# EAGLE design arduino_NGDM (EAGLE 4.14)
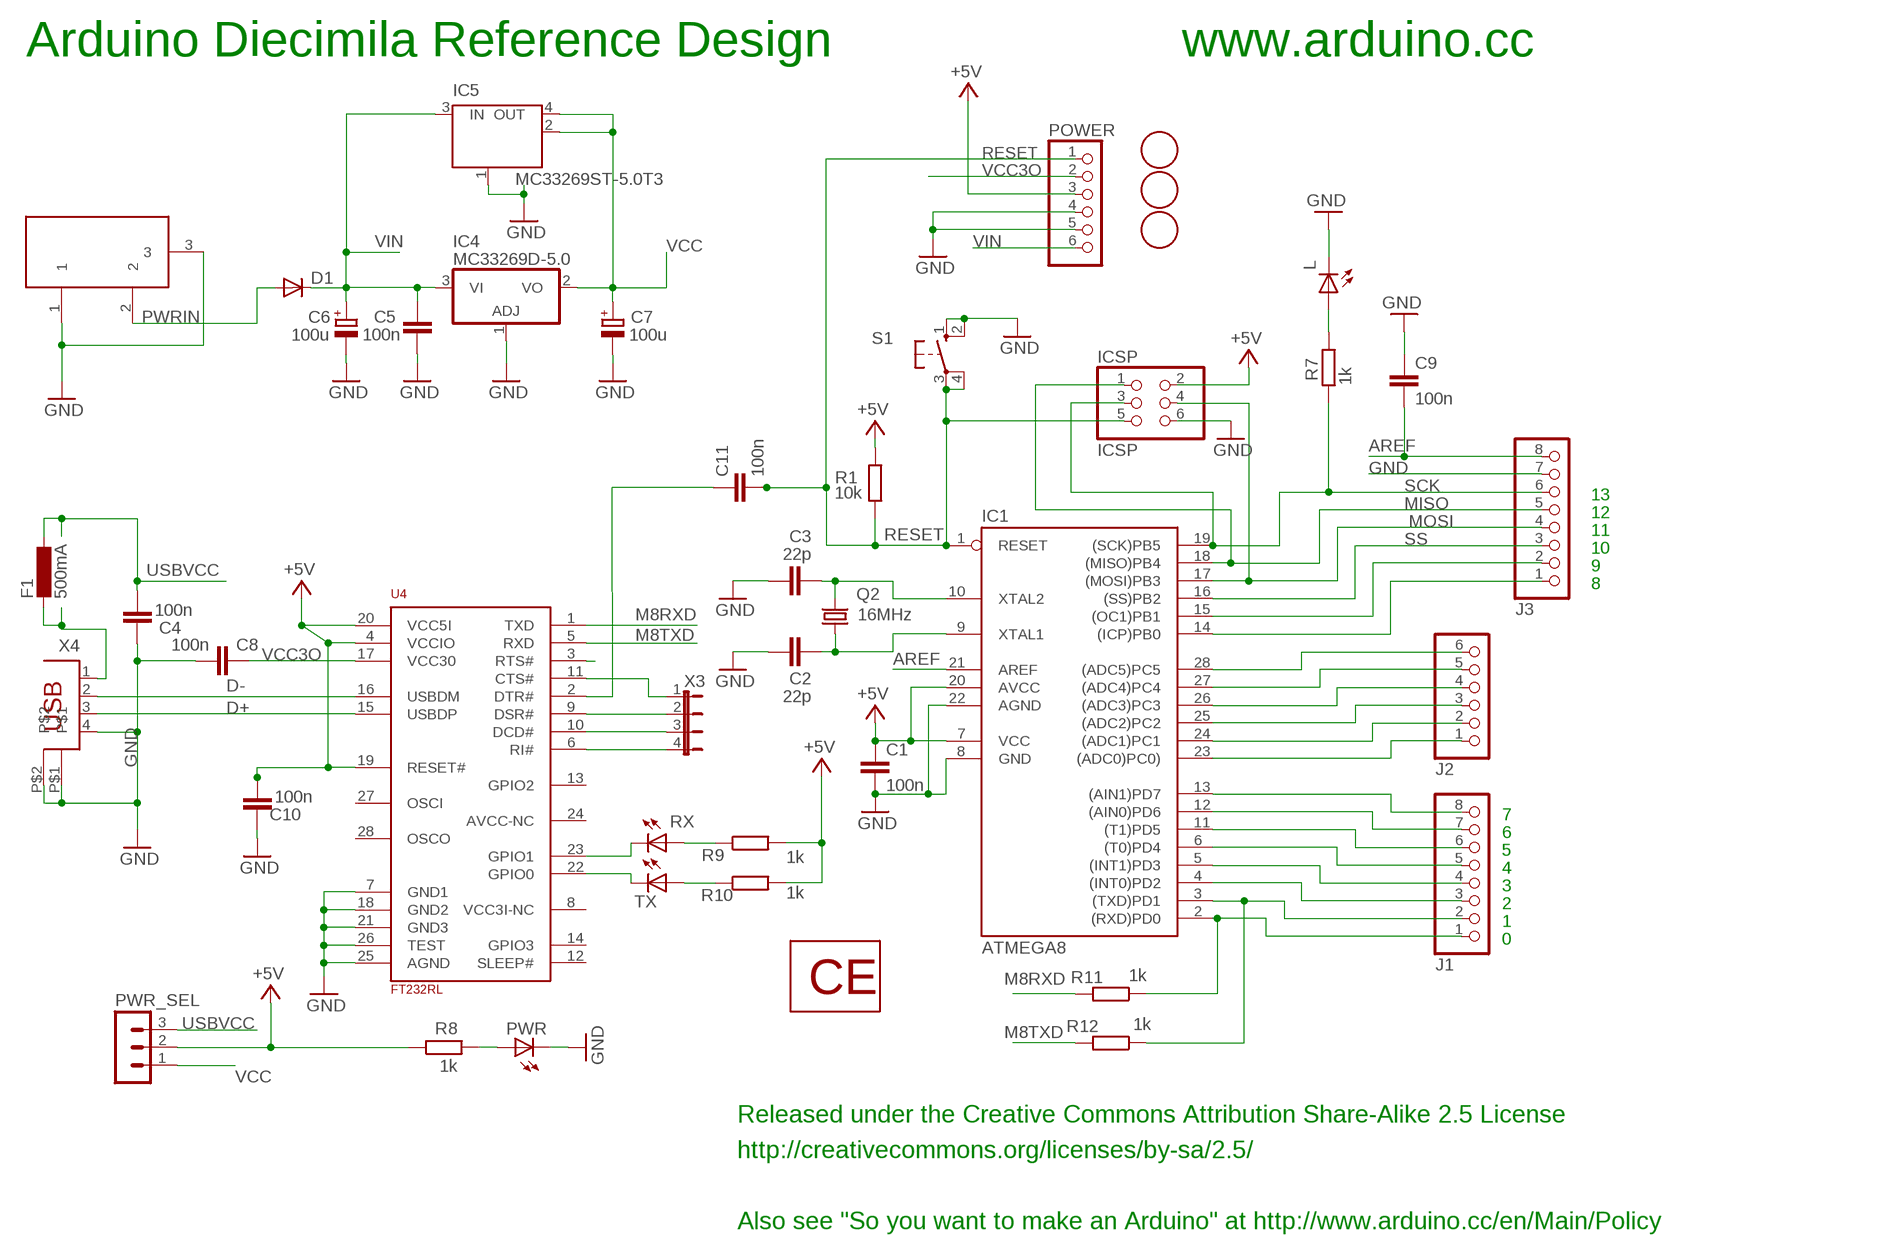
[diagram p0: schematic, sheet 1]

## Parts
C1  100n  C-EU  [C0805RND]
C2  22p  C-EU  [C0805RND]
C3  22p  C-EU  [C0805RND]
C4  100n  C-EU  [C0805RND]
C5  100n  C-EU  [C0805RND]
C6  100u  CPOL-EUD  [PANASONIC_D]
C7  100u  CPOL-EUD  [PANASONIC_D]
C8  100n  C-EU  [C0805RND]
C9  100n  C-EU  [C0805RND]
C10  100n  C-EU  [C0805RND]
C11  100n  C-EU  [C0805RND]
D1  DIODE-SMB  [SMB]
F1  500mA  L-EUL1812  [L1812]
IC1  ATMEGA8  AT90S4433P  [DIL28-3]
IC4  MC33269D-5.0  [DPACK]
IC5  MC33269ST-5.0T3  MC33269ST-3.3T3  [SOT223]
ICSP  ICSP  PINHD-2X3  [2X03]
J1  PINHD-1X8  [1X08]
J2  PINHD-1X6  [1X06]
J3  PINHD-1X8  [1X08]
L  LED0805ROUND  [0805RND]
POWER  PINHD-1X6  [1X06]
PWR  LED0805ROUND  [0805RND]
PWR_SEL  MA03-1  [MA03-1]
Q2  16MHz  CRYTALHC49S  [HC49/S]
R1  10k  R-EU_  [R0805RND]
R7  1k  R-EU_  [R0805RND]
R8  1k  R-EU_  [R0805RND]
R9  1k  R-EU_  [R0805RND]
R10  1k  R-EU_  [R0805RND]
R11  1k  R-EU_  [R0805RND]
R12  1k  R-EU_  [R0805RND]
RX  LED0805ROUND  [0805RND]
S1  10-XX  [B3F-10XX]
TX  LED0805ROUND  [0805RND]
U4  FT232RL  [SSOP28]
U$1  FIDUCIALMOUNT  [FIDUCIA-MOUNT]
U$2  FIDUCIALMOUNT  [FIDUCIA-MOUNT]
U$3  FIDUCIALMOUNT  [FIDUCIA-MOUNT]
U$4  CE  [CE-COPPER]
X2  DC21MMX  [DC-21MM]
X3  JP4E  [JP4]
X4  PN61729  [PN61729]

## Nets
+5V [usbvcc]: C1.1 C10.1 IC1.7(VCC) IC1.20(AVCC) ICSP.2 POWER.3 PWR_SEL.2 R1.2 R8.1 R9.2 R10.2 U4.4(VCCIO) U4.19(RESET#) U4.20(VCC5I)
AREF [aref]: C9.2 IC1.21(AREF) J3.8
D+: U4.15(USBDP) X4.3
D-: U4.16(USBDM) X4.2
GND [gnd]: C1.2 C2.1 C3.1 C4.2 C5.1 C6.- C7.- C8.1 C9.1 C10.2 IC1.8(GND) IC1.22(AGND) IC4.1(ADJ) IC5.1(GND/ADJ) ICSP.6 J3.7 L.P$2(C) POWER.4 POWER.5 PWR.P$2(C) S1.1(S) S1.2(S1) U4.7(GND1) U4.18(GND2) U4.21(GND3) U4.25(AGND) U4.26(TEST) X2.1 X2.3 X4.4 X4.P$1 X4.P$2
M8RXD: R11.2 U4.1(TXD)
M8TXD: R12.2 U4.5(RXD)
MISO: IC1.18((MISO)PB4) ICSP.1 J3.5
MOSI: IC1.17((MOSI)PB3) ICSP.4 J3.4
N$2: L.P$1(A) R7.1
N$3: PWR.P$1(A) R8.2
N$5: IC1.14((ICP)PB0) J3.1
N$6: C2.2 IC1.9(XTAL1) Q2.1
N$7: C3.2 IC1.10(XTAL2) Q2.2
N$8 [usbvcc]: F1.2 X4.1
N$9: U4.3(RTS#)
N$10: IC1.4((INT0)PD2) J1.3
N$11: IC1.5((INT1)PD3) J1.4
N$12: IC1.6((T0)PD4) J1.5
N$13: IC1.11((T1)PD5) J1.6
N$14: IC1.12((AIN0)PD6) J1.7
N$15: IC1.13((AIN1)PD7) J1.8
N$16: IC1.23((ADC0)PC0)) J2.1
N$17: IC1.24((ADC1)PC1) J2.2
N$18: IC1.25((ADC2)PC2) J2.3
N$19: IC1.26((ADC3)PC3) J2.4
N$20: IC1.27((ADC4)PC4) J2.5
N$21: IC1.28((ADC5)PC5) J2.6
N$22: IC1.15((OC1)PB1) J3.2
N$24: C11.1 U4.2(DTR#)
N$32: RX.P$2(C) U4.23(GPIO1)
N$34: TX.P$2(C) U4.22(GPIO0)
N$35: R9.1 RX.P$1(A)
N$36: R10.1 TX.P$1(A)
N$37: U4.6(RI#) X3.4
N$38: U4.10(DCD#) X3.3
N$39: U4.11(CTS#) X3.1
N$40: U4.9(DSR#) X3.2
PD0: IC1.2((RXD)PD0) J1.1 R11.1
PD1: IC1.3((TXD)PD1) J1.2 R12.1
PWRIN [power]: D1.A X2.2
RESET: C11.2 IC1.1(RESET) ICSP.5 POWER.1 R1.1 S1.3(P) S1.4(P1)
SCK: IC1.19((SCK)PB5) ICSP.3 J3.6 R7.2
SS: IC1.16((SS)PB2) J3.3
USBVCC [usbvcc]: C4.1 F1.1 PWR_SEL.3
VCC [usbvcc]: C7.+ IC4.2(VO) IC5.2(OUT) IC5.4(OUT) PWR_SEL.1
VCC3O: C8.2 POWER.2 U4.17(VCC30)
VIN [power]: C5.2 C6.+ D1.C IC4.3(VI) IC5.3(IN) POWER.6
Unconnected: U4.8(VCC3I-NC) U4.12(SLEEP#) U4.13(GPIO2) U4.14(GPIO3) U4.24(AVCC-NC) U4.27(OSCI) U4.28(OSCO)

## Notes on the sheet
- Arduino Diecimila Reference Design | www.arduino.cc
- 13
- 12
- 11
- 10
- 9
- 8
- 7
- 6
- 5
- 4
- 3
- 2
- 1
- 0
- Released under the Creative Commons Attribution Share-Alike 2.5 License
- http://creativecommons.org/licenses/by-sa/2.5/
- Also see "So you want to make an Arduino" at http://www.arduino.cc/en/Main/Policy

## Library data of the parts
C1-C5 C8-C11 = rcl:C-EU: CAPACITOR, European symbol
C6 C7 = rcl:CPOL-EU: POLARIZED CAPACITOR, European symbol
D1 = diode:DIODE-: DIODE
F1 = rcl:L-EU: INDUCTOR, European symbol
IC1 = atmel:AT90S4433: MICROCONTROLLER 4 Kbytes FLASH 128 bytes SRAM 256 bytes EEPROM UART 6-channel 10 bit ADC
IC4 = linear:MC33269?*: Adjustable Output Low Dropout Voltage Regulator 800 mA Source: http://www.onsemi.com/pub/Collateral/MC33269-D.PDF
IC5 = linear:MC33269ST*: Adjustable Output Low Dropout Voltage Regulator 800 mA Source: http://www.onsemi.com/pub/Collateral/MC33269-D.PDF
ICSP = pinhead:PINHD-2X3: PIN HEADER
J1 J3 = pinhead:PINHD-1X8: PIN HEADER
J2 POWER = pinhead:PINHD-1X6: PIN HEADER
L PWR RX TX = led:LED: LED
PWR_SEL = con-lstb:MA03-1: PIN HEADER
Q2 = crystal:CRYTAL: CRYSTAL
R1 R7-R12 = rcl:R-EU_: RESISTOR, European symbol
S1 = switch-omron:10-XX: OMRON SWITCH
U4 = SmartPrj:FT232RL
U$1-U$3 = SmartPrj:FIDUCIALMOUNT
U$4 = SmartPrj:CE
X2 = powersupply:DC21MM
X3 = jumper:JP4E: JUMPER
X4 = SmartPrj:PN61729: BERG USB connector

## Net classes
0 default: width 0.254 mm, drill 0.254 mm
1 power: width 0.61 mm, drill 0.33 mm, clearance 0.711 mm
2 gnd: width 0.305 mm, drill 0.254 mm, clearance 0.711 mm
3 usbvcc: width 0.508 mm, drill 0.254 mm, clearance 0.711 mm
4 aref: width 0.406 mm

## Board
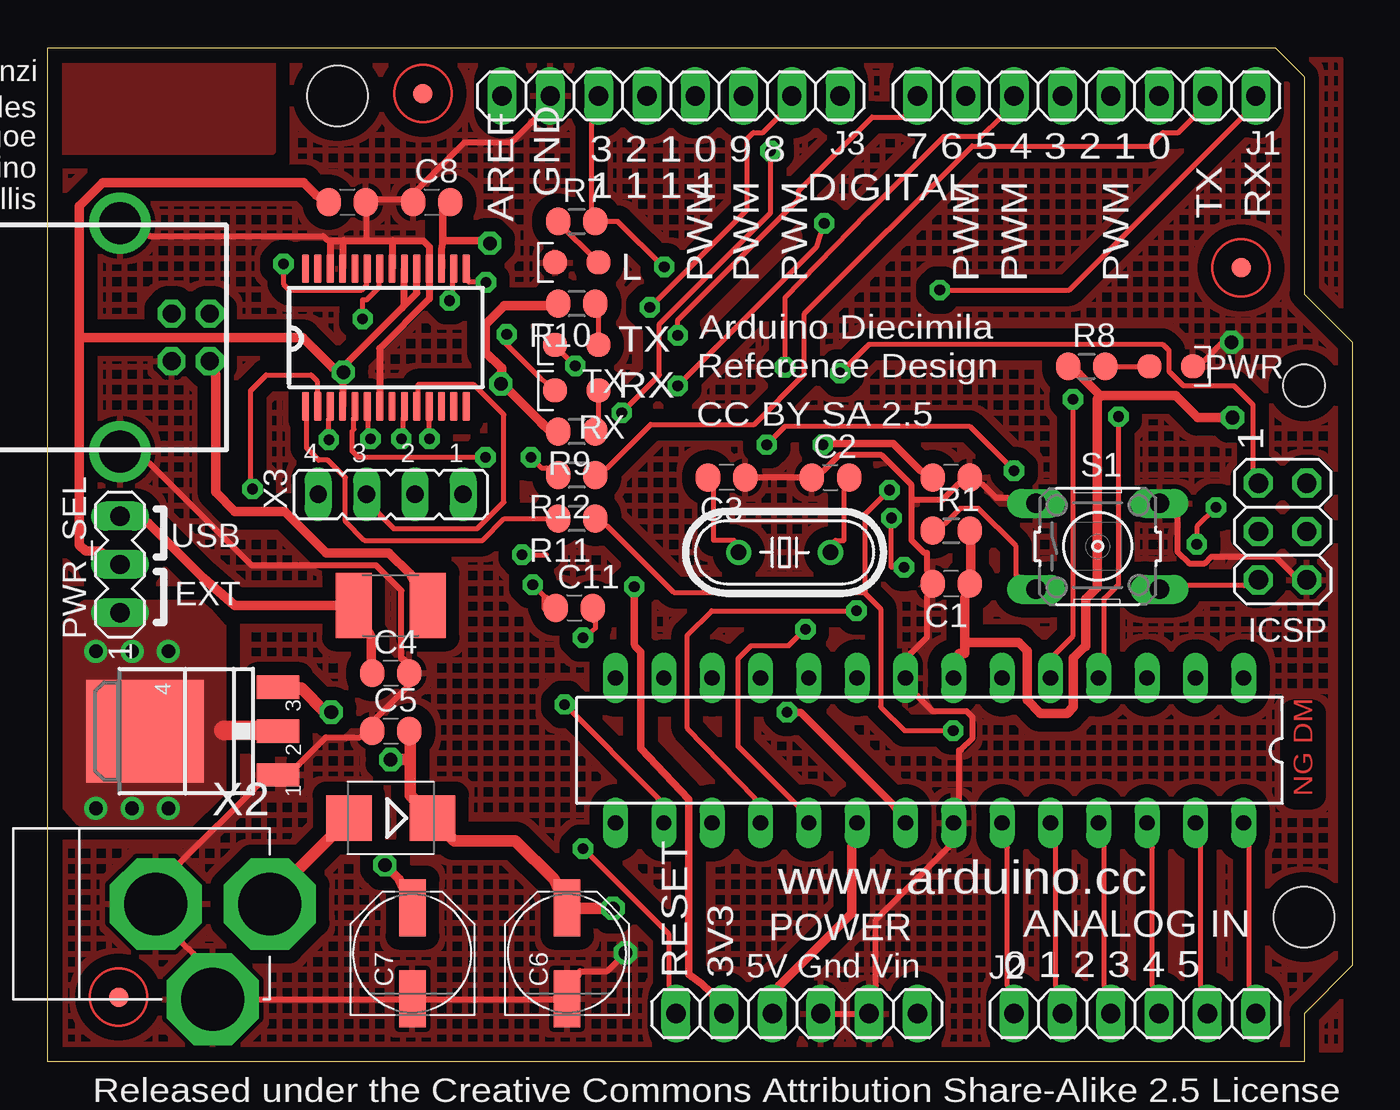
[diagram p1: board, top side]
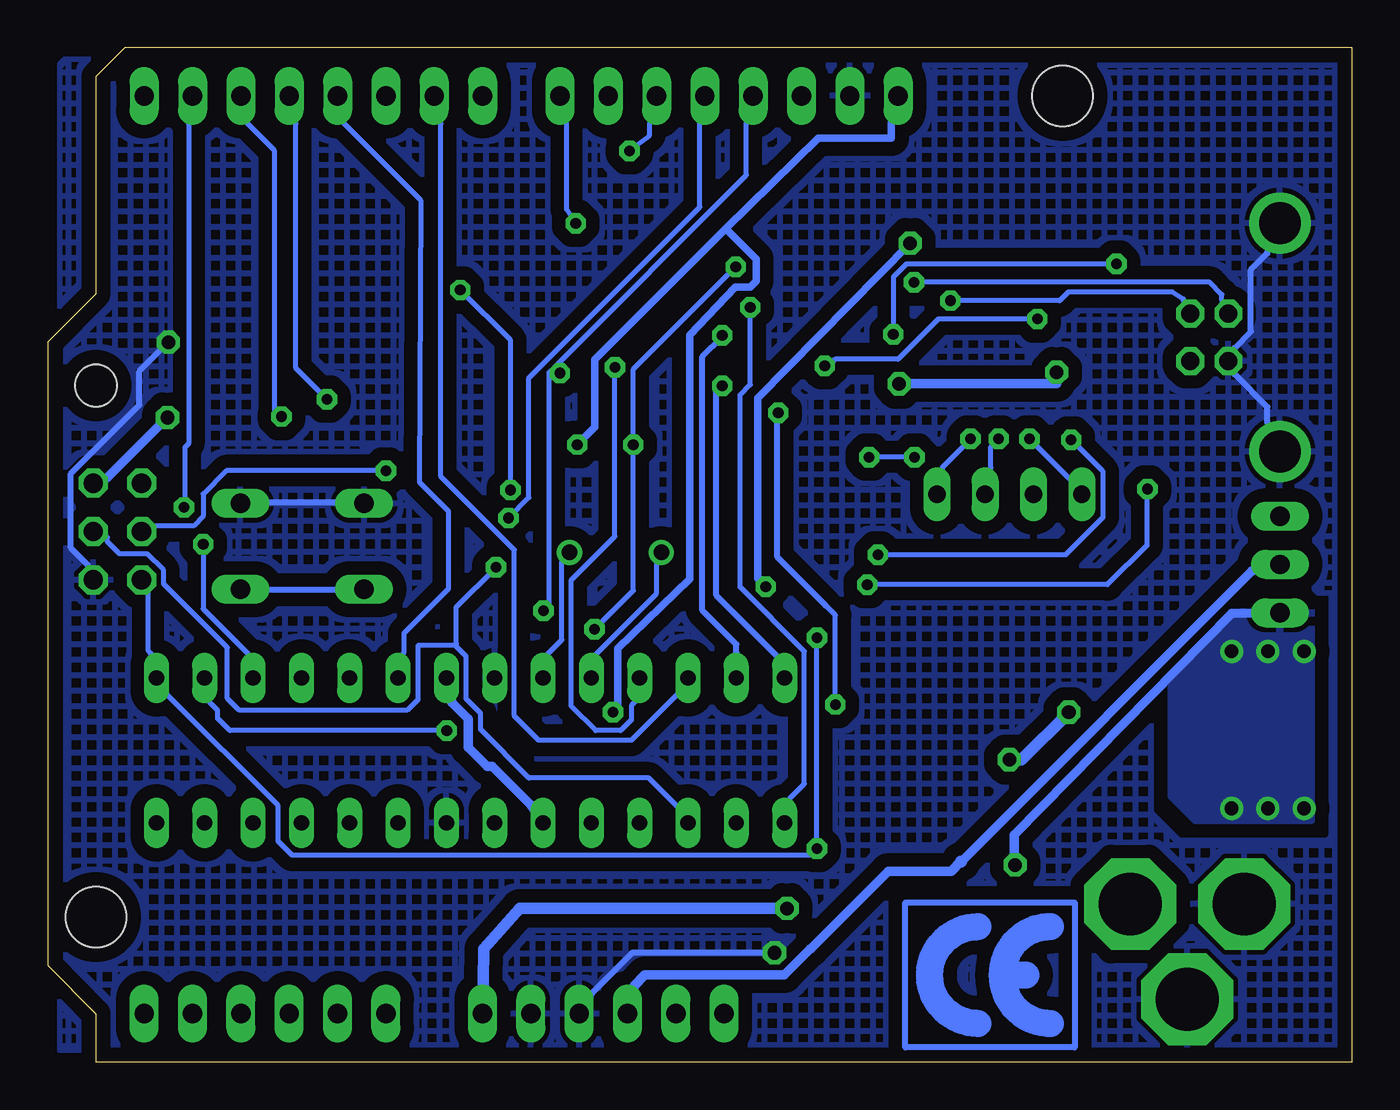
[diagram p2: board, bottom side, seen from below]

Size 68.58 x 53.34 mm. Coordinates in mm from the lower left corner, seen from the top.
Outline: 0,53.34 64.52,53.34 66.04,51.82 66.04,40.39 68.58,37.85 68.58,5.08 66.04,2.54 66.04,0 0,0 0,53.34
Copper layers (1*16): Top 0.035mm / dielectric 1.5mm / Bottom 0.035mm
Design rules "default": minimum track width 10mil, minimum drill 22mil, track to track 10mil, track to pad 10mil, pad to pad 10mil, via to via 16mil, smd to smd 8mil, copper to edge 30mil, drill to drill 12mil, minimum pad ring 10mil, minimum via ring 10mil, stop-mask expansion 4mil, vias tented up to drill 0mil, thermal gap 10mil
Holes 2.2 mm at 66.04,35.56
Holes 3.2 mm at 66.04,7.62 15.24,50.8
vRestrict: area 22.9,44.1 to 24.6,49.1; area 25.4,45.5 to 27.1,49.1; area 28.4,45.3 to 29.6,48.8; area 31,45.3 to 32.1,48.8; area 33.5,45.3 to 34.7,48.8; area 36.1,45.3 to 37.2,48.8; area 38.7,47.2 to 39.9,48.8; area 40.3,45.1 to 47.6,46.9; area 33.4,41 to 34.9,44.6; area 35.9,41 to 37.5,44.6; area 38.5,41 to 40,44.6; area 47.5,41 to 49,44.6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

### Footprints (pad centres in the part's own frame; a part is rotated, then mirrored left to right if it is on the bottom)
C0805RND = smd 1.3 x 1.5: 1 -0.977,0; 2 0.977,0
PANASONIC_D = smd 3 x 1.4: + 2.4,0; - -2.4,0
SMB = smd 2.4 x 2.4: A 2.2,0; C -2.2,0
L1812 = smd 1.9 x 3.4: 1 -1.95,0; 2 1.95,0
DIL28-3 = drill 0.813 long: 1 -16.51,-3.81; 2 -13.97,-3.81; 3 -11.43,-3.81; 4 -8.89,-3.81; 5 -6.35,-3.81; 6 -3.81,-3.81; 7 -1.27,-3.81; 8 1.27,-3.81; 9 3.81,-3.81; 10 6.35,-3.81; 11 8.89,-3.81; 12 11.43,-3.81; 13 13.97,-3.81; 14 16.51,-3.81; 15 16.51,3.81; 16 13.97,3.81; 17 11.43,3.81; 18 8.89,3.81; 19 6.35,3.81; 20 3.81,3.81; 21 1.27,3.81; 22 -1.27,3.81; 23 -3.81,3.81; 24 -6.35,3.81; 25 -8.89,3.81; 26 -11.43,3.81; 27 -13.97,3.81; 28 -16.51,3.81
DPACK = smd 1 x 1.6: 1 -2.28,-4.8; 3 2.28,-4.8 | smd 5.4 x 6.2: 2 0,2.5
SOT223 = smd 1.219 x 2.235: 1 -2.311,-3.099; 2 0,-3.099; 3 2.311,-3.099 | smd 3.6 x 2.2: 4 0,3.099
2X03 = drill 1.016 octagon: 1 -2.54,-1.27; 2 -2.54,1.27; 3 0,-1.27; 4 0,1.27; 5 2.54,-1.27; 6 2.54,1.27
1X08 = drill 1.016 long: 1 -8.89,0; 2 -6.35,0; 3 -3.81,0; 4 -1.27,0; 5 1.27,0; 6 3.81,0; 7 6.35,0; 8 8.89,0
1X06 = drill 1.016 long: 1 -6.35,0; 2 -3.81,0; 3 -1.27,0; 4 1.27,0; 5 3.81,0; 6 6.35,0
0805RND = smd 1.27 x 1.27: P$1 -1.143,0; P$2 1.143,0
MA03-1 = drill 1.016 long: 1 -2.54,0; 2 0,0; 3 2.54,0
HC49/S = drill 0.813 round: 1 -2.413,0; 2 2.413,0
R0805RND = smd 1.3 x 1.5: 1 -0.977,0; 2 0.977,0
B3F-10XX = drill 1.016 long: 1 -3.251,2.261; 2 3.251,2.261; 3 -3.251,-2.261; 4 3.251,-2.261
SSOP28 = smd 0.381 x 1.499: 1 -4.225,-3.625; 2 -3.575,-3.625; 3 -2.925,-3.625; 4 -2.275,-3.625; 5 -1.625,-3.625; 6 -0.975,-3.625; 7 -0.325,-3.625; 8 0.325,-3.625; 9 0.975,-3.625; 10 1.625,-3.625; 11 2.275,-3.625; 12 2.925,-3.625; 13 3.575,-3.625; 14 4.225,-3.625; 15 4.225,3.625; 16 3.575,3.625; 17 2.925,3.625; 18 2.275,3.625; 19 1.625,3.625; 20 0.975,3.625; 21 0.325,3.625; 22 -0.325,3.625; 23 -0.975,3.625; 24 -1.625,3.625; 25 -2.275,3.625; 26 -2.925,3.625; 27 -3.575,3.625; 28 -4.225,3.625
FIDUCIA-MOUNT = smd 1.016 x 1.016: P$1 0,0
DC-21MM = drill 3.302 pad 4.826 octagon: 1 -5.08,-3.353; 2 -0.076,-6.35; 3 -0.076,-0.356
JP4 = drill 0.914 long: 1 -3.81,0; 2 -1.27,0; 3 1.27,0; 4 3.81,0
PN61729 = drill 0.95 octagon: 1 1.25,4.71; 2 -1.25,4.71; 3 -1.25,2.71; 4 1.25,2.71 | drill 2.2 round: P$1 -6,0; P$2 6,0

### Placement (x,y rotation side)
C1  47.5,25.15 180 top
C2  41.15,30.73 0 top
C3  35.69,30.73 180 top
C4  18.03,20.45 0 top
C5  18.03,17.4 0 top
C6  27.3,5.71 90 top
C7  19.18,5.71 90 top
C8  20.19,45.21 0 top
C9  47.5,30.73 180 top
C10  15.75,45.21 0 top
C11  27.69,23.88 0 top
D1  18.03,12.83 180 top
F1  18.03,24 0 top
IC1  46.35,16.38 180 top
IC4  7.62,17.4 90 top
IC5  9.02,17.4 90 top
ICSP  64.91,27.89 270 top
J1  54.61,50.8 180 top
J2  57.15,2.54 0 top
J3  32.77,50.8 180 top
L  27.81,42.04 180 top
POWER  39.37,2.54 0 top
PWR  59.05,36.58 0 top
PWR_SEL  3.81,26.16 90 top
Q2  38.73,26.8 180 top
R1  47.5,27.94 0 top
R7  27.81,44.2 0 top
R8  54.61,36.58 0 top
R9  27.81,33.15 180 top
R10  27.81,39.88 180 top
R11  27.81,28.57 180 top
R12  27.81,30.86 180 top
RX  27.81,35.31 180 top
S1  55.2,27.11 0 top
TX  27.81,37.72 180 top
U4  17.78,38.1 0 top
U$1  19.73,50.92 0 top
U$2  62.73,41.76 0 top
U$3  3.73,3.41 0 top
U$4  23.5,0.76 0 bottom
X2  5.33,8.38 90 top
X3  18.03,29.84 180 top
X4  3.81,38.1 270 top

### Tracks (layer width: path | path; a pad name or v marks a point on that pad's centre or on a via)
+5V  (via drill 0.71)
  Top 0.381: U4.4 15.51,36.27 15.51,36.54 18.59,39.62 | 18.59,39.62 19.41,40.44 U4.19 19.41,41.68 | U4.20 18.75,39.79 18.59,39.62
  Top 0.508: 23.88,36.47 23.01,37.34 23.01,38.78 24.01,39.78 26.21,39.78 R10.2 | 23.88,36.47 23.88,35.69 25.91,33.66 26.39,33.2 R9.2 | v23.82,35.66 23.88,36.47 | 15.51,36.27 v15.54,36.27 14.99,36.52 13.41,38.1 1.68,38.1 | 1.68,38.1 1.68,45.01 2.9,46.23 13.46,46.23 14.12,45.57 C10.1 | 1.68,38.1 1.68,27.19 1.99,26.87 2.69,26.87 PWR_SEL.2 | 55.32,35.05 54.2,36.17 R8.1 | 55.32,35.05 59.28,35.05 60.45,33.88 v62.28,33.88 | R1.2 48.51,27.23 48.51,25.86 C1.1 48.21,24.43 48.21,22.05 | 48.21,22.05 48.21,21.49 47.9,21.49 IC1.7 | POWER.3 38.46,4.01 42.27,7.82 42.27,11.28 IC1.20 | 55.32,35.05 55.17,34.85 55.17,24.94 54.56,24.33 54.56,21.84 54.51,21.84 53.9,21.23 53.9,18.66 53.58,18.34 52.17,18.34 51.49,19.02 51.49,21.6 51.04,22.05 48.21,22.05
  Bottom 0.406: 28.47,5.94 28.5,5.94
  Bottom 0.508: v23.82,35.66 15.54,35.66 v15.54,36.27 | v62.28,33.88 65.43,30.73 ICSP.2 | IC1.20 43.18,13.51 45.21,15.54 45.48,15.54 46.48,16.55 46.48,18.03 47.35,18.9 IC1.7 | 20.56,10.53 5.28,25.81 PWR_SEL.2 | 28.5,5.94 29.87,4.57 37.19,4.57 37.74,4.01 POWER.3 | 28.47,5.94 24.38,10.03 21.08,10.03 20.57,10.54
  Bottom 0.61: 20.56,10.53 20.57,10.54
AREF  (via drill 0.56)
  Top 0.406: v40.74,32.46 40.79,32.51 44.45,32.51 45.87,31.09 C9.2 | v38.86,18.39 39.57,18.39 44.45,13.51 IC1.21
  Bottom 0.406: v40.74,32.46 39.83,33.38 39.83,36.93 32.94,43.81 | 32.94,43.81 28.07,48.56 24.23,48.56 24.23,49.33 J3.8 | v38.86,18.39 38.61,18.64 38.61,21.74 34.82,25.4 34.82,38.23 32.44,40.74 31.66,40.74 31.34,41.06 31.34,42.22 32.94,43.81
D+  (via drill 0.56)
  Top 0.254: v23.04,41 22.15,41 U4.15
  Bottom 0.254: v23.04,41 7.49,41 6.86,40.36 6.86,40.03 X4.3
D-  (via drill 0.56)
  Top 0.254: v21.13,40.03 21.29,40.03 21.29,41 U4.16
  Bottom 0.254: v21.13,40.03 15.39,40.03 14.94,40.49 9.46,40.49 8.88,40.12 X4.2
GND  (via drill 0.71)
  Top 0.305: POWER.4 POWER.5 43.54,4.01 43.54,7.47 47.35,11.28 IC1.22 47.9,13.87 47.9,16.41 48.01,16.41 48.62,17.02 48.62,18.12 48.3,18.44 46.53,18.44 45.72,19.25 IC1.8 45.36,21.49 46.23,22.35 46.23,24.43 C1.2 46.23,25.86 46.23,26.77 46.08,26.77 45.41,27.43 45.41,29.57 | v62.23,37.85 61.77,37.85 60.81,36.88 PWR.P$2 | C3.1 C2.1 40.79,31.09 41.6,31.9 43.84,31.9 45.41,30.33 45.41,29.57 | S1.1 50.44,29.67 49.84,29.67 49.12,30.38 C9.1 47.85,30.38 47.04,29.57 45.41,29.57 | ICSP.6 65.43,25.65 64.52,26.57 61.16,26.57 60.81,26.21 59.99,26.21 59.38,26.82 59.38,28.65 S1.2 | 16.76,43.18 16.76,44.5 C10.2 17.37,45.36 18.59,45.36 C8.1 19.23,45.67 21.92,48.36 24.38,48.36 25.7,49.68 J3.7 | 14.86,43.18 14.68,43.23 14.48,43.43 5.38,43.43 X4.P$1 | IC4.1 12.45,15.14 IC5.1 | IC5.1 13.21,15.65 14.63,17.07 16.41,17.07 C5.1 17.32,18.14 18.9,19.71 C4.2 18.75,21.18 18.59,21.18 18.59,24.79 17.27,26.11 10.72,26.11 5.38,31.45 X4.P$2 | IC5.1 11.02,14.53 6.96,10.46 6.91,10.46 X2.3 7.06,6.3 7.67,5.69 X2.1 18.49,3.3 C7.- 19.86,3.3 26.62,3.3 C6.- 27.99,4.78 29.41,4.78 v30.38,5.74
  Top 0.381: U4.7 17.45,37.52 20.07,40.13 20.07,41.73 20.06,41.73 U4.18 20.05,41.78 20.07,41.78 20.07,42.86 19.75,43.18 18.16,43.18 | U4.21 18.11,43.18 18.16,43.18 | U4.26 14.86,43.18 15.62,43.18 | 18.16,43.18 16.76,43.18 15.62,43.18 | U4.25 15.51,43.18 15.62,43.18
  Bottom 0.305: v62.23,37.85 63.75,36.32 63.75,34.54 67.36,30.94 67.36,27.03 66.45,26.11 ICSP.6 | S1.2 56.95,29.41 53.44,29.41 S1.1 | X4.P$2 4.47,33.68 4.47,34.44 6.2,36.17 X4.4 6.2,37.54 5.33,38.41 5.33,41.66 4.47,42.52 X4.P$1 | v30.38,5.74 37.85,5.74 39.93,3.66 POWER.4
  pour Bottom (isolate 0.406, rank 2, hatched): 0.64,52.7 67.69,52.7 67.94,52.45 67.94,0.64 0.89,0.64 0.64,0.89
  pour Top (isolate 0.406, rank 2, hatched): 0.64,52.7 67.94,52.7 67.94,0.64 0.64,0.64
M8RXD
  Top 0.254: U4.1 13.61,33.73 13.61,32.28 14.25,31.65 14.73,31.65 15.65,30.73 15.65,28.43 16.65,27.43 22.86,27.43 24,28.57 R11.2
M8TXD  (via drill 0.56)
  Top 0.254: v23.01,31.8 16.32,31.8 16,32.12 16,33.17 16.1,33.27 16.1,33.73 U4.5 | v25.4,31.8 25.96,31.24 26.21,31.24 R12.2
  Bottom 0.254: v23.01,31.8 v25.4,31.8
MISO  (via drill 0.56)
  Top 0.254: v42.52,23.72 34.9,23.72 33.63,22.45 33.63,17.55 37.19,13.87 IC1.18 | v41.66,36.22 43.18,37.74 58.61,37.74 58.93,37.43 58.93,36.32 59.69,35.56 62.35,35.56 63.35,34.56 63.35,31.19 ICSP.1
  Bottom 0.254: v42.52,23.72 42.22,24.03 42.22,36.27 41.94,36.55 | 41.94,36.55 31.85,46.63 31.85,49.33 J3.5 | v41.66,36.22 41.86,36.42 41.86,36.47 41.94,36.55
MOSI  (via drill 0.56)
  Top 0.254: v44.35,28.6 44.35,26.01 v45.01,26.01
  Bottom 0.254: 47.14,21.89 46.58,21.34 46.58,19.1 45.82,18.34 45.82,17.48 43.28,14.94 36.98,14.94 35.56,13.51 IC1.17 | 47.14,21.89 49.12,21.89 49.12,19.05 49.68,18.49 58.5,18.49 59.13,19.13 59.13,21.79 62.48,25.15 62.48,25.86 63.35,26.72 64.8,26.72 65.43,27.36 65.43,27.58 ICSP.4 | v44.35,28.6 43.28,29.67 43.28,35.97 34.29,44.96 34.29,49.33 J3.4 | v45.01,26.01 47.09,23.93 47.09,22 47.14,21.89
N$2
  Top 0.254: R7.1 26.8,44.2 L.P$1
N$3
  Top 0.254: R8.2 PWR.P$1
N$5  (via drill 0.56)
  Top 0.254: v33.12,35.56 40.44,42.88 v40.82,44.09
  Bottom 0.254: 33.43,35.26 v33.12,35.56 | v40.82,44.09 41.3,44.83 41.3,49.33 J3.1
  Bottom 0.305: 33.43,35.26 33.43,24.54 29.72,20.83 29.72,20.19 IC1.14
N$6
  Top 0.254: C2.2 41.86,30.02 41.86,27.43 41.4,27.43 Q2.1
  Bottom 0.254: IC1.9 42.27,21.49 41.55,22.2 41.55,26.31 Q2.1
N$7
  Top 0.254: C3.2 35,30.02 35,27.43 36.07,27.43 Q2.2
  Bottom 0.254: IC1.10 39.73,21.49 36.58,24.64 36.58,26.16 Q2.2
N$8
  Top 0.508: X4.1 8.84,36.17 8.84,29.96 9.84,28.96 12.47,28.96 14.66,26.77 17.93,26.77 19.05,25.65 F1.2
N$9  (via drill 0.56)
  Top 0.254: v14.78,32.72 14.78,33.73 U4.3 | v24.94,26.67 26.21,26.67
  Bottom 0.254: v14.78,32.72 13.11,31.04 13.11,28.65 15.09,26.67 v24.94,26.67
N$10  (via drill 0.56)
  Top 0.254: v56.29,33.93 56.29,25.09 55.58,24.38 55.52,24.38 55.52,21.49 IC1.4
  Bottom 0.254: v56.29,33.93 56.64,34.29 56.64,47.9 58.06,49.33 J1.3
N$11  (via drill 0.56)
  Top 0.254: v53.9,34.85 53.9,22.4 52.98,21.49 IC1.5
  Bottom 0.254: v53.9,34.85 55.52,36.47 55.52,49.33 J1.4
N$12
  Bottom 0.254: IC1.6 49.89,21.49 49.84,21.54 49.84,22.55 47.5,24.89 47.5,28.96 49.02,30.48 48.95,45.29 52.98,49.33 J1.5
N$13  (via drill 0.56)
  Top 0.254: v38.76,36.52 38.76,40.18 43.08,44.63 47.12,48.67 49.07,48.67 50.09,49.68 J1.6
  Bottom 0.254: v38.76,36.52 38.76,27.64 41.05,25.35 41.05,18.69 39.78,17.42 38.46,17.42 37.9,17.98 37.9,18.75 37.74,18.9 IC1.11
N$14
  Bottom 0.254: IC1.12 35.56,19.25 37.9,16.92 42.77,16.92 44.04,18.19 44.04,26.92 47.9,30.79 47.9,49.33 J1.7
N$15  (via drill 0.56)
  Top 0.254: v33.12,38.2 33.12,39.01 39.47,45.36 39.47,45.82 42.55,48.9 | 42.55,48.9 42.52,48.87 | 42.55,48.9 43.33,49.68 45.01,49.68 J1.8
  Bottom 0.254: IC1.13 32.44,20.19 32.31,21.49
  Bottom 0.305: v33.12,38.2 33.12,38.12 34.16,37.08 34.16,23.75 32.38,21.97 32.44,20.19
N$16
  Top 0.254: IC1.23 50.44,11.28 50.44,4.01 J2.1
N$17
  Top 0.254: IC1.24 52.98,11.28 52.98,4.01 J2.2
N$18
  Top 0.254: IC1.25 55.52,11.28 55.52,4.01 J2.3
N$19
  Top 0.254: IC1.26 58.06,11.28 58.06,4.01 J2.4
N$20
  Top 0.254: IC1.27 60.6,11.28 60.6,4.01 J2.5
N$21
  Top 0.254: IC1.28 63.14,11.28 63.14,4.01 J2.6
N$22  (via drill 0.56)
  Top 0.254: v31.65,39.67 36.78,44.81 36.78,48.55 37.1,48.87 37.59,48.87 38.41,49.68 J3.2
  Bottom 0.254: v31.65,39.67 31.65,35.61 32.18,35.08 32.18,24.97 28.8,21.59 28.8,14.63 29.57,13.87 IC1.15
N$24  (via drill 0.56)
  Top 0.254: v10.77,30.12 10.67,30.12 10.67,35.31 11.48,36.12 13.86,36.12 14.17,35.8 14.17,35.2 U4.2 | v25.5,25.09 26.21,24.38
  Top 0.406: 26.21,24.38 26.16,24.38 26.16,23.88 C11.1
  Bottom 0.254: v25.5,25.09 12.88,25.09 10.79,27.18 10.79,30.1 v10.77,30.12 10.67,30.23
N$27
  pour Top: 0.64,52.58 11.81,52.58 11.81,47.88 0.64,47.88
N$32  (via drill 0.56)
  Top 0.254: v24.13,38.25 24.13,37.72 25.91,35.94 26.49,35.51 RX.P$2 | v12.39,41.96 12.39,40.91 12.71,40.59 16.51,40.59 16.76,40.84 16.76,41 U4.23
  Bottom 0.254: v24.13,38.25 24.13,41.27 23.44,41.96 v12.39,41.96
N$34  (via drill 0.56)
  Top 0.254: v27.74,36.6 27.03,37.31 TX.P$2 | v16.56,39.06 16.56,40.08 16.76,40.08 17.42,40.74 17.42,41 U4.22
  Bottom 0.254: v16.56,39.06 21.77,39.06 23.88,36.96 27.18,36.96 27.41,36.73 | 27.41,36.73 27.81,36.7 | 27.41,36.73 v27.74,36.6
N$35
  Top 0.254: RX.P$1 28.96,33.88 R9.1
N$36
  Top 0.254: TX.P$1 28.96,39.42 R10.1
N$37  (via drill 0.56)
  Top 0.254: v16.97,32.77 16.87,32.77 16.87,33.73 U4.6
  Bottom 0.254: v16.97,32.77 14.88,30.68 X3.4
N$38
  Top 0.254: U4.10 19.46,35.2 19.46,35.61 22.4,35.61 23.98,34.04 23.98,29.44 22.58,28.04 18.19,28.04 17.42,28.8 X3.3
N$39  (via drill 0.56)
  Top 0.254: v20.07,32.77 20.07,33.73 U4.11
  Bottom 0.254: v20.07,32.77 21.54,31.29 21.54,31.24 X3.1
N$40  (via drill 0.56)
  Top 0.254: v18.59,32.77 18.69,32.77 18.69,33.73 U4.9
  Bottom 0.254: v18.59,32.77 19,32.36 19,31.24 X3.2
PD0  (via drill 0.56)
  Top 0.254: 42.93,24.69 32.92,24.69 29.41,28.19 R11.1 | 42.93,24.69 43.79,23.82 43.79,18.68 45.04,17.42 v47.6,17.42 | v46.89,40.59 53.7,40.59 62.79,49.68 J1.1 | v44.25,30.07 42.98,28.8 42.98,24.79 42.93,24.69
  Bottom 0.254: v47.6,17.42 59,17.42 59.64,18.06 59.64,18.49 60.05,18.9 IC1.2 | v46.89,40.59 44.25,37.95 v44.25,30.07
PD1  (via drill 0.56)
  Top 0.254: R12.1 29.41,31.24 31.7,33.53 37.13,33.53 39.78,36.17 39.78,39.35 48.59,48.16 57.91,48.16 58.62,48.87 59.44,48.87 60.25,49.68 J1.2 | v60.4,27.23 60.4,28.14 v61.42,29.16
  Bottom 0.254: v60.4,27.23 60.4,23.82 58.06,21.49 IC1.3 | v61.42,29.16 61.37,29.21 61.37,32.31 61.16,32.51 61.16,49.33 J1.2
PWRIN
  Top 0.61: D1.A 14.68,11.63 13.21,10.16 X2.2
RESET  (via drill 0.56)
  Top 0.254: R1.1 47.14,28.3 47.95,29.11 48.92,29.11 50.9,27.13 50.9,25.6 S1.3 | S1.4 59.94,25.04 62.89,25.04 ICSP.5 | 28.8,23.77 28.8,22.81 v28.14,22.3 | v28.14,11.23 32.66,6.71 32.66,4.01 POWER.1
  Top 0.406: 28.8,23.77 28.7,23.27 28.7,23.88 C11.2
  Bottom 0.254: ICSP.5 63.3,24.64 63.3,21.64 63.14,21.49 IC1.1 62.23,19.25 56.46,13.49 56.46,11.61 55.73,10.87 28.5,10.87 v28.14,11.23 v28.14,22.3
  Bottom 0.305: S1.4 58.42,24.83 58.42,24.77 58.33,24.85 S1.3
SCK  (via drill 0.56)
  Top 0.254: v39.83,22.76 38.96,21.89 36.98,21.89 36.3,21.21 36.3,16.59 39.37,13.51 IC1.19 | v50.8,31.09 48.46,33.43 38.76,33.43 v37.8,32.46 | 28.6,47.37 28.6,49.33 J3.6 | 28.6,47.37 28.57,47.37 | 28.6,47.37 28.6,44.3 28.7,44.2 R7.2 29.97,44.2 32.38,41.78 v32.41,41.81
  Bottom 0.254: v32.41,41.81 37.8,36.42 v37.8,32.46 37.8,24.79 v39.83,22.76 | v50.8,31.09 59.18,31.09 60.4,29.87 60.4,28.7 60.91,28.19 62.89,28.19 ICSP.3
SS  (via drill 0.56)
  Top 0.254: v27.18,18.8 32.11,13.87 IC1.16 | v30.18,34.14 32.16,36.12 32.16,38.81 38,44.65 v38,47.9
  Bottom 0.254: v27.18,18.8 27.18,23.5 27.69,24 | v38,47.9 36.93,48.72 36.93,49.33 J3.3
  Bottom 0.305: 27.69,24 30.23,26.54 30.23,34.16 30.2,34.14 v30.18,34.14
USBVCC
  Top 0.508: C4.1 17.02,21.18 17.02,22.35 F1.1 9.83,24 8.18,25.45 5.28,28.35 PWR_SEL.3
VCC  (via drill 0.71)
  Top 0.508: 11.02,17.42 IC5.2 | v17.73,10.36 18.49,9.6 C7.+
  Top 1.016: 9.27,17.42 11.02,17.42
  Bottom 0.508: v17.73,10.36 17.73,10.41 17.78,10.41 17.78,11.94 6.35,23.57 PWR_SEL.1
  other vias: 2.54,21.59 4.45,21.59 6.35,21.59 2.54,13.34 4.45,13.34 6.35,13.34
  pour Top (isolate 0.305, no thermals): 8,12.57 9.27,13.72 9.27,22.86 8.13,24.13 1.91,24.13 0.64,22.73 0.64,13.72 1.65,12.57
  pour Bottom: 2.16,12.7 2.16,24.13 5.71,24.13 9.53,20.32 9.53,13.97 8.26,12.7
VCC3O  (via drill 0.56, 0.71)
  Top 0.254: 30.89,21.84 30.84,21.97
  Top 0.381: 20.78,43.18 20.7,42.72 U4.17
  Top 0.406: C8.2 20.78,44.76 20.78,43.18 23.11,43.18 v23.24,43.05 | 30.84,21.97 v30.84,24.99 | 30.89,21.84 31.17,21.57 31.17,16.48 33.71,13.82 33.71,4.62 34.39,4.12 34.85,3.66 POWER.2
  Bottom 0.406: v23.24,43.05 31.27,34.9 31.27,25.43 v30.84,24.99
VIN  (via drill 0.71)
  Top 0.61: IC4.3 12.45,19.71 IC5.3 13.34,19.66 14.61,18.39 v14.91,18.39 | 19.05,15.9 19.05,14.02 D1.C 21.39,11.63 24.59,11.63 26.62,9.6 C6.+ 27.99,8.08 v29.72,8.08 | 19.05,15.9 19.05,16.66 C5.2 | v18.03,15.9 19.05,15.9
  Bottom 0.61: v14.91,18.39 14.91,18.36 17.4,15.88 v18.03,15.9 | v29.72,8.08 43.76,8.08 45.64,5.94 POWER.6

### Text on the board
Top: NG DM
tNames: M.Banzi | D.Cuartielles | T.Igoe | G.Martino | 3 2 1 0 9 8 | 7 6 5 4 3 2 1 0 | D.Mellis | GND | 1 1 1 1 | DIGITAL | AREF | TX | RX | PWM | PWM | PWM | PWM | PWM | PWM | Arduino Diecimila | TX | Reference Design | RX | CC BY SA 2.5 | 1 | USB | EXT | www.arduino.cc | ANALOG IN | RESET | 3V3 | 5V Gnd Vin | 0 1 2 3 4 5 | Released under the Creative Commons Attribution Share-Alike 2.5 License | http://creativecommons.org/licenses/by-sa/2.5/
tStop: MADE IN | ITALY
Reference: C8 | R7 | R10 | R8 | R9 | C3 | C2 | R12 | R11 | R1 | R2 | C1 | R3 | C4 | C5 | X2 | C7 | C6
